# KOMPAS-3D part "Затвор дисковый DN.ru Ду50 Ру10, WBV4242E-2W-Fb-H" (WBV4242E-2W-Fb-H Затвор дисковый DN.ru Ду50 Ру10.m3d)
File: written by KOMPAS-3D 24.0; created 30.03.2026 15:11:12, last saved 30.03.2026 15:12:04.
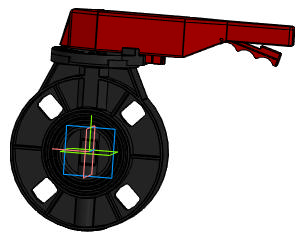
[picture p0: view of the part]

Document properties: Автор: R2D2; Полное имя файла: E:\Работа\Зайцев\WBV4242E-2W-Fb-H Затвор дисковый DN.ru Ду50-200 Ру10\DN50\WBV4242E-2W-Fb-H Затвор дисковый DN.ru Ду50 Ру10.m3d

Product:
- Part/product: Затвор дисковый DN.ru Ду50 Ру10  | designation WBV4242E-2W-Fb-H
    Масса: 1.17
    Раздел спецификации: Прочие изделия
    Примечание: D050-81197

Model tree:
1. Операция без истории:1

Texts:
  WBV4242E-2W-Fb-H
